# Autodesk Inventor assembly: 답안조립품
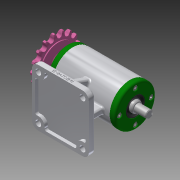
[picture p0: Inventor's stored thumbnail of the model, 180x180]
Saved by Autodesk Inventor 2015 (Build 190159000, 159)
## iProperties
Created: 2019-06
Part Number: 답안조립품
Document SubType Name: Assembly
Designer: a-20
Author: a-20
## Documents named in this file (11)
- C:\Users\a-20\Desktop\490604V1014\답안조립품.iam
- C:\Users\a-20\Desktop\490604V1014\본체.ipt
- C:\Users\a-20\Desktop\490604V1014\커버.ipt
- C:\Users\a-20\Desktop\490604V1014\베어링 6203.ipt
- C:\Users\a-20\Desktop\490604V1014\축.ipt
- C:\Users\a-20\Desktop\490604V1014\키 4x4x12.ipt
- C:\Users\a-20\Desktop\490604V1014\스프로킷.ipt
- C:\Users\a-20\Desktop\490604V1014\평와셔.ipt
- C:\Users\a-20\Desktop\490604V1014\볼트 M4.ipt
- C:\Users\a-20\Desktop\490604V1014\스프링와셔.ipt
- C:\Users\a-20\Desktop\490604V1014\오일 실 17 30 5.ipt
